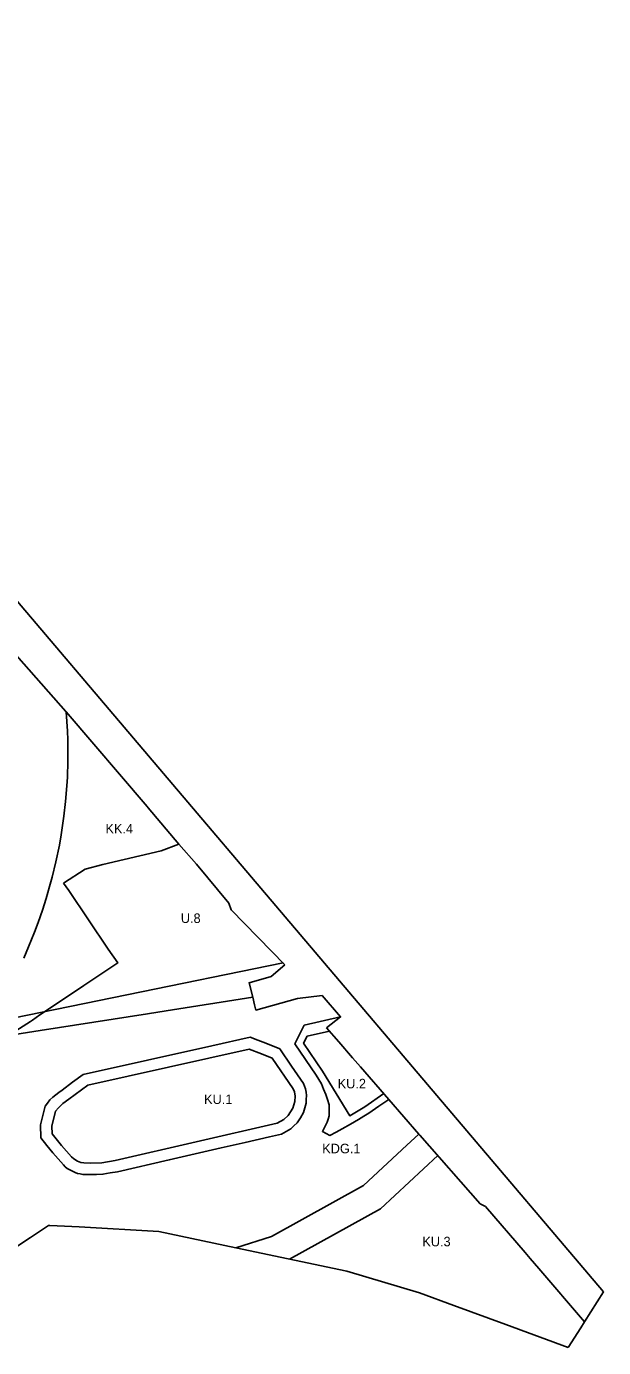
# Model space of a CAD drawing. Extents: x 7424719 to 7426158, y 5545504 to 5546892.
# Drawn here: x 7425675 to 7425978, y 5545504 to 5546198 of the extents above; entities that cross this region are included whole.
import ezdxf

# ---------------------------------------------------------------- set-up
doc = ezdxf.new("R2010")
doc.units = 0
for name, color, linetype in [('Linia Zabudowy Nieprzekraczalna', 7, 'Continuous'), ('Linie Rozgraniczajace', 7, 'Continuous'), ('Oznaczenia Przeznaczenia', 7, 'Continuous')]:
    doc.layers.add(name, color=color, linetype=linetype)

msp = doc.modelspace()

# ---------------------------------------------------------------- linework, layer by layer
at = {"layer": 'Linia Zabudowy Nieprzekraczalna'}
for points in [[(7425592.45, 5545657.95), (7425598.08, 5545661.94), (7425600.26, 5545662.54), (7425611.3, 5545665.5), (7425627.63, 5545668.96), (7425628.68, 5545669.19), (7425632.77, 5545670.07), (7425645.71, 5545672.72), (7425810.15, 5545706.28)], [(7425834.49, 5545670.45), (7425822.73, 5545667.82), (7425820.87, 5545664.1), (7425830.8, 5545649.52), (7425845.13, 5545626.07), (7425847.81, 5545627.6), (7425853.07, 5545630.75), (7425862.98, 5545637.67)], [(7425891.34, 5545605.17), (7425861.32, 5545577.21), (7425813.47, 5545550.77)]]:
    msp.add_lwpolyline(points, dxfattribs=at)
msp.add_lwpolyline([(7425792.34, 5545661.03), (7425707.63, 5545642.11), (7425697.65, 5545634.71), (7425694.5, 5545632.43), (7425692.1, 5545630.28), (7425690.64, 5545628.4), (7425688.72, 5545620.58), (7425688.82, 5545616.57), (7425693.75, 5545610.44), (7425699.01, 5545604.42), (7425700.19, 5545603.35), (7425702.16, 5545602.29), (7425703.89, 5545601.52), (7425705.46, 5545601.27), (7425708.88, 5545601.16), (7425714.88, 5545601.35), (7425721.92, 5545602.55), (7425807.09, 5545622.08), (7425810.6, 5545624.06), (7425812.85, 5545626.16), (7425815.32, 5545630.12), (7425816.24, 5545633.61), (7425816.4, 5545636.41), (7425816.08, 5545638.7), (7425815.5, 5545640.25), (7425804.48, 5545656.24), (7425798.79, 5545658.52)], close=True, dxfattribs=at)
at = {"layer": 'Linie Rozgraniczajace'}
for p, q in [((7425978.47, 5545533.55), (7425205.67, 5546443.4)), ((7425821.16, 5545673.62), (7425840.36, 5545677.91)), ((7425839.41, 5545664.8), (7425832.96, 5545672.21)), ((7425881.79, 5545533.1), (7425881.84, 5545533.09))]:
    msp.add_line(p, q, dxfattribs=at)
for points in [[(7425696.1, 5545838.33), (7425651.74, 5545888.31), (7425651.34, 5545899.61)], [(7425696.28, 5545838.12), (7425696.95, 5545827.96), (7425697.01, 5545823.47), (7425697.11, 5545817.12), (7425697.09, 5545816.12), (7425696.99, 5545810.92), (7425696.88, 5545804.99), (7425696.81, 5545803.86), (7425696.66, 5545801.62), (7425696.23, 5545794.99), (7425695.8, 5545791), (7425694.99, 5545783.38), (7425693.61, 5545773.61), (7425692.67, 5545768.08), (7425690.79, 5545759.35), (7425688.84, 5545751.35), (7425687.51, 5545746.34), (7425685.68, 5545740.13), (7425683.71, 5545734.01), (7425681.49, 5545727.56), (7425679.63, 5545722.52), (7425676.45, 5545714.71), (7425673.93, 5545708.84)], [(7425781.69, 5545737.61), (7425764.62, 5545758.12), (7425755.33, 5545768.64), (7425739.32, 5545787.69), (7425738.69, 5545788.43), (7425696.28, 5545838.12), (7425696.1, 5545838.33)], [(7425755.33, 5545768.64), (7425746.04, 5545765.23), (7425715.4, 5545757.98), (7425706.23, 5545755.52), (7425694.74, 5545748.1)], [(7425694.74, 5545748.1), (7425697.53, 5545744.32), (7425718.27, 5545713.46), (7425723.27, 5545706.27), (7425705.53, 5545694.49), (7425701.55, 5545691.85), (7425682.3, 5545679.07), (7425678.48, 5545676.23), (7425677.43, 5545675.46), (7425665.92, 5545668.13)], [(7425781.69, 5545737.61), (7425782.88, 5545734.17), (7425811.02, 5545705.32)], [(7425811.02, 5545705.32), (7425803.86, 5545699.09), (7425792.3, 5545695.85), (7425794.21, 5545688.27), (7425795.19, 5545684.36), (7425795.89, 5545681.55), (7425817.66, 5545687.58), (7425830.73, 5545689.27)], [(7425748.67, 5545681.12), (7425794.21, 5545688.27)], [(7425832.96, 5545672.21), (7425840.36, 5545677.91), (7425830.73, 5545689.27)], [(7425655.55, 5545666.5), (7425665.92, 5545668.13), (7425682.53, 5545670.74), (7425738.91, 5545679.59), (7425748.67, 5545681.12)], [(7425821.16, 5545673.62), (7425816.24, 5545663.79), (7425827.43, 5545647.35), (7425828.83, 5545645.07), (7425830.23, 5545642.78), (7425831.44, 5545639.99), (7425832.64, 5545637.21), (7425833.49, 5545634.51), (7425834.34, 5545631.82), (7425834.32, 5545628.9), (7425834.29, 5545625.98), (7425833.81, 5545624.34), (7425833.33, 5545622.69), (7425832.07, 5545620.24), (7425830.8, 5545617.79), (7425832.78, 5545616.77), (7425834.77, 5545615.74), (7425837.93, 5545617.46), (7425841.1, 5545619.17), (7425845.46, 5545621.66), (7425849.83, 5545624.15), (7425852.54, 5545625.77), (7425855.25, 5545627.39), (7425860.43, 5545631.01), (7425865.62, 5545634.63)], [(7425792.82, 5545667.29), (7425772.72, 5545662.8), (7425705.08, 5545647.69), (7425699.59, 5545643.62), (7425694.11, 5545639.55), (7425692.42, 5545638.33), (7425690.73, 5545637.11), (7425689.21, 5545635.75), (7425687.7, 5545634.39), (7425686.41, 5545632.74), (7425685.12, 5545631.08), (7425683.91, 5545626.16), (7425682.7, 5545621.23), (7425682.88, 5545614.39), (7425686.02, 5545610.48), (7425689.15, 5545606.58), (7425691.94, 5545603.39), (7425694.73, 5545600.2), (7425695.72, 5545599.31), (7425696.71, 5545598.42), (7425698.11, 5545597.65), (7425699.51, 5545596.89), (7425700.84, 5545596.31), (7425702.18, 5545595.72), (7425703.53, 5545595.5), (7425704.88, 5545595.29), (7425706.88, 5545595.22), (7425708.88, 5545595.16), (7425712.18, 5545595.26), (7425715.48, 5545595.37), (7425719.29, 5545596.02), (7425723.1, 5545596.67), (7425750.34, 5545602.91), (7425777.59, 5545609.16), (7425790.29, 5545612.08), (7425803, 5545614.99), (7425806.14, 5545615.71), (7425809.28, 5545616.43), (7425811.72, 5545617.81), (7425814.17, 5545619.18), (7425815.85, 5545620.75), (7425817.53, 5545622.32), (7425819.21, 5545625.02), (7425820.88, 5545627.72), (7425821.54, 5545630.19), (7425822.2, 5545632.66), (7425822.31, 5545634.66), (7425822.42, 5545636.66), (7425822.18, 5545638.42), (7425821.93, 5545640.18), (7425821.39, 5545641.62), (7425820.86, 5545643.05), (7425814.63, 5545652.1), (7425808.4, 5545661.14), (7425800.99, 5545664.1)], [(7425800.99, 5545664.1), (7425796.9, 5545665.69), (7425792.82, 5545667.29)], [(7425968.47, 5545517.8), (7425944.46, 5545545.83), (7425939.93, 5545551.13), (7425937.32, 5545554.18), (7425916.39, 5545578.41), (7425913.69, 5545579.74), (7425881.98, 5545615.81), (7425881.43, 5545616.44), (7425865.62, 5545634.63), (7425850.71, 5545651.79), (7425846.62, 5545656.5), (7425839.41, 5545664.8)], [(7425785.28, 5545556.73), (7425804.11, 5545562.73), (7425852.45, 5545589.45), (7425875.13, 5545610.57), (7425881.43, 5545616.44)], [(7425635.03, 5545548.39), (7425647.38, 5545548.68), (7425658.39, 5545549.4), (7425669.8, 5545557.01), (7425677.41, 5545562.08), (7425686.97, 5545568.45)], [(7425686.97, 5545568.45), (7425687.66, 5545568.42), (7425703.1, 5545567.77)], [(7425703.1, 5545567.77), (7425744.79, 5545565.3), (7425785.28, 5545556.73), (7425843.56, 5545544.4), (7425881.79, 5545533.1)], [(7425881.84, 5545533.09), (7425899.76, 5545526.46), (7425927.12, 5545516.4), (7425959.92, 5545504.34)], [(7425959.92, 5545504.34), (7425966.52, 5545514.73), (7425968.47, 5545517.8), (7425978.47, 5545533.55)]]:
    msp.add_lwpolyline(points, dxfattribs=at)

# ---------------------------------------------------------------- texts
at = {"layer": 'Oznaczenia Przeznaczenia'}
for s, p in [('KK.4', (7425716.84, 5545774.28)), ('U.8', (7425756.42, 5545727.27)), ('KU.2', (7425838.8, 5545640.44)), ('KU.1', (7425768.65, 5545632.21)), ('KDG.1', (7425830.69, 5545606.35)), ('KU.3', (7425883.27, 5545557.5))]:
    msp.add_text(s, height=5, dxfattribs=at).set_placement(p)

doc.saveas('drawing.dxf')
